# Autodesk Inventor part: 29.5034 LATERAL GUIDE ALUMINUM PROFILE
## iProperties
Created: 2007-07
Part Number: 29.5034 LATERAL GUIDE ALUMINUM PROFILE
Document SubType Name: Modeling
Designer: Andy Moles
Material: Aluminum-6061
Author: Andy Moles
